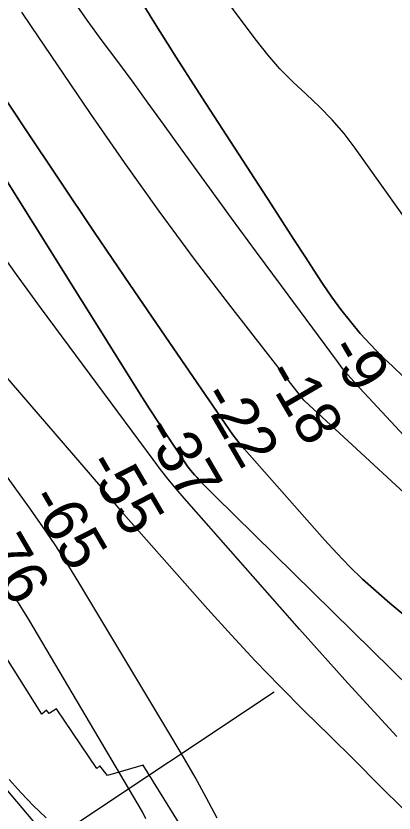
# Model space of a CAD drawing. Extents: x 3297753 to 3335611, y 652252 to 677623.
# Drawn here: x 3309808 to 3310374, y 670586 to 671780 of the extents above; entities that cross this region are included whole.
import ezdxf

# ---------------------------------------------------------------- set-up
doc = ezdxf.new("R2010")
doc.units = 0
for name, color, linetype in [('V-CHAN-NAID', 7, 'Continuous'), ('V-RIVR-RANG', 7, 'Continuous'), ('V-RRAP-RVMT', 7, 'Continuous'), ('V-TOPO-DPTH', 7, 'Continuous'), ('V-TOPO-MAJR', 7, 'Continuous'), ('V-TOPO-MINR', 7, 'Continuous')]:
    doc.layers.add(name, color=color, linetype=linetype)

msp = doc.modelspace()

# ---------------------------------------------------------------- linework, layer by layer
at = {"layer": 'V-RIVR-RANG'}
msp.add_line((3308878.8, 669892.6), (3310194.6, 670767.2), dxfattribs=at)
at = {"layer": 'V-RRAP-RVMT'}
for p, q in [((3309846.4, 670733.9), (3309768.1, 670857.3)), ((3309853.8, 670739.8), (3309846.4, 670733.9)), ((3309857.6, 670735.1), (3309853.8, 670739.8)), ((3309868.4, 670742.1), (3309857.6, 670735.1)), ((3309928.8, 670652.6), (3309868.4, 670742.1)), ((3309933.3, 670656.4), (3309928.8, 670652.6)), ((3309945.1, 670642.1), (3309933.3, 670656.4)), ((3309998.2, 670657.4), (3309945.1, 670642.1)), ((3310074.3, 670535.2), (3309998.2, 670657.4))]:
    msp.add_line(p, q, dxfattribs=at)
at = {"layer": 'V-TOPO-DPTH'}
for points in [[(3309973.3, 671839), (3310010.5, 671777.9), (3310048.4, 671717.3), (3310086.9, 671657.1), (3310189.9, 671498), (3310207, 671471.5), (3310224.2, 671445), (3310241.4, 671418.5), (3310258.5, 671392), (3310267.8, 671377.7), (3310280.8, 671358.7), (3310294.3, 671340.1), (3310308.6, 671322.1), (3310323.4, 671304.5), (3310339, 671287.6), (3310354.9, 671271), (3310371.5, 671255.1), (3310388.4, 671239.5)], [(3310388.4, 671239.5), (3310371.5, 671255.1), (3310354.9, 671271), (3310339, 671287.6), (3310323.4, 671304.5), (3310308.6, 671322.1), (3310294.3, 671340.1), (3310280.8, 671358.7), (3310267.8, 671377.7), (3310258.5, 671392), (3310241.4, 671418.5), (3310224.2, 671445), (3310207, 671471.5), (3310189.9, 671498), (3310086.9, 671657.1), (3310048.4, 671717.3), (3310010.5, 671777.9), (3309973.3, 671839)], [(3309610, 671826.9), (3309979.7, 671235.6), (3309993.7, 671213.3), (3310007.9, 671191.2), (3310022.3, 671169.2), (3310036.8, 671147.2), (3310065.1, 671104.7), (3310065.6, 671104.1), (3310066.9, 671102.3), (3310075.3, 671092.6), (3310079, 671088.4), (3310082.7, 671084.3), (3310086.5, 671080.2), (3310090.3, 671076.3), (3310094.2, 671072.3), (3310098.2, 671068.4), (3310102.1, 671064.5), (3310106, 671060.6), (3310458.1, 670714.2)], [(3310458.1, 670714.2), (3310106, 671060.6), (3310102.1, 671064.5), (3310098.2, 671068.4), (3310094.2, 671072.3), (3310090.3, 671076.3), (3310086.5, 671080.2), (3310082.7, 671084.3), (3310079, 671088.4), (3310075.3, 671092.6), (3310066.9, 671102.3), (3310065.6, 671104.1), (3310065.1, 671104.7), (3310036.8, 671147.2), (3310022.3, 671169.2), (3310007.9, 671191.2), (3309993.7, 671213.3), (3309979.7, 671235.6), (3309610, 671826.9)], [(3309698.7, 671796.3), (3309820.8, 671612.2), (3309873, 671533.9), (3309925.5, 671455.8), (3309978.3, 671377.9), (3310031.3, 671300.1), (3310127.3, 671160.2), (3310132.7, 671152.6), (3310138.2, 671145.2), (3310144.1, 671138), (3310150.1, 671130.9), (3310269.8, 670995), (3310288.3, 670974.9), (3310307.2, 670955.3), (3310326.9, 670936.4), (3310347.1, 670918), (3310367.8, 670900.2), (3310388.8, 670882.7)], [(3310388.8, 670882.7), (3310367.8, 670900.2), (3310347.1, 670918), (3310326.9, 670936.4), (3310307.2, 670955.3), (3310288.3, 670974.9), (3310269.8, 670995), (3310150.1, 671130.9), (3310144.1, 671138), (3310138.2, 671145.2), (3310132.7, 671152.6), (3310127.3, 671160.2), (3310031.3, 671300.1), (3309978.3, 671377.9), (3309925.5, 671455.8), (3309873, 671533.9), (3309820.8, 671612.2), (3309698.7, 671796.3)], [(3310552.4, 670914.9), (3310246.5, 671197.5), (3310245.7, 671198.2), (3310243.9, 671199.7), (3310243.1, 671200.4), (3310239.9, 671203.3), (3310239.1, 671204.2), (3310238.8, 671204.6), (3310129.6, 671344.8), (3310075.4, 671415.8), (3310022.1, 671487.5), (3309970.3, 671560.3), (3309919.4, 671633.8), (3309831, 671764.2), (3309816.6, 671785.7)], [(3310552.4, 670914.9), (3310246.5, 671197.5), (3310245.7, 671198.2), (3310243.9, 671199.7), (3310243.1, 671200.4), (3310239.9, 671203.3), (3310239.1, 671204.2), (3310238.8, 671204.6), (3310129.6, 671344.8), (3310075.4, 671415.8), (3310022.1, 671487.5), (3309970.3, 671560.3), (3309919.4, 671633.8), (3309831, 671764.2), (3309816.6, 671785.7)]]:
    msp.add_lwpolyline(points, dxfattribs=at)
at = {"layer": 'V-TOPO-MAJR'}
msp.add_lwpolyline([(3310378.3, 670700.6), (3310305, 670780.4), (3310232.6, 670861.2), (3310059.7, 671057.6), (3310047.6, 671071.7), (3310035.8, 671086), (3310024.3, 671100.6), (3310013.1, 671115.4), (3309844.7, 671343), (3309808.5, 671392.6), (3309772.7, 671442.5), (3309737.4, 671492.7), (3309702.5, 671543.3), (3309700.5, 671546.2), (3309667.1, 671595.6), (3309633.8, 671645), (3309600.8, 671694.7), (3309567.9, 671744.4), (3309527.8, 671805.6)], dxfattribs=at)
at = {"layer": 'V-TOPO-MINR'}
for points in [[(3308758.8, 672065.7), (3308996.7, 671601), (3308998.4, 671597.8), (3309000.1, 671594.6), (3309001.9, 671591.5), (3309003.7, 671588.4), (3309017.8, 671565.5), (3309020.8, 671560.8), (3309024, 671556.2), (3309027.4, 671551.7), (3309030.9, 671547.4), (3309034.6, 671543.2), (3309594.9, 670863.7), (3309602.6, 670851.4), (3309610.7, 670839.4), (3309619.3, 670827.8), (3309628.4, 670816.5), (3309932.1, 670456.8)], [(3310388.4, 671239.5), (3310371.5, 671255.1), (3310354.9, 671271), (3310339, 671287.6), (3310323.4, 671304.5), (3310308.6, 671322.1), (3310294.3, 671340.1), (3310280.8, 671358.7), (3310267.8, 671377.7), (3310258.5, 671392), (3310241.4, 671418.5), (3310224.2, 671445), (3310207, 671471.5), (3310189.9, 671498), (3310086.9, 671657.1), (3310048.4, 671717.3), (3310010.5, 671777.9), (3309973.3, 671839)], [(3310458.1, 670714.2), (3310106, 671060.6), (3310102.1, 671064.5), (3310098.2, 671068.4), (3310094.2, 671072.3), (3310090.3, 671076.3), (3310086.5, 671080.2), (3310082.7, 671084.3), (3310079, 671088.4), (3310075.3, 671092.6), (3310066.9, 671102.3), (3310065.6, 671104.1), (3310065.1, 671104.7), (3310036.8, 671147.2), (3310022.3, 671169.2), (3310007.9, 671191.2), (3309993.7, 671213.3), (3309979.7, 671235.6), (3309610, 671826.9)], [(3310473.8, 671360.4), (3310315.9, 671581.9), (3310299.3, 671603.7), (3310281.6, 671624.6), (3310262.5, 671644.1), (3310242.4, 671662.8), (3310222.3, 671681.5), (3310203, 671700.9), (3310185.1, 671721.6), (3310167.9, 671743), (3310143.4, 671775.9), (3310115.4, 671814.9)], [(3310436, 671100.4), (3310322.2, 671222.6), (3310313.6, 671232.2), (3310305.2, 671241.9), (3310297.1, 671252), (3310289.3, 671262.2), (3310205.3, 671375.6), (3310168, 671426.2), (3310130.8, 671476.9), (3310093.8, 671527.8), (3310057, 671578.7), (3310028.7, 671618.1), (3310006, 671649.4), (3309983.2, 671680.6), (3309960.3, 671711.6), (3309937.2, 671742.6), (3309914.5, 671773.8), (3309892.5, 671805.5)], [(3310389.2, 670590.5), (3310352, 670627.7), (3310314.8, 670664.8), (3310277.4, 670701.8), (3310239.9, 670738.6), (3310202.8, 670775.9), (3310166.2, 670813.6), (3310130.4, 670852.1), (3310095.2, 670891.1), (3309976.3, 671025.6), (3309968.9, 671034.1), (3309961.7, 671042.8), (3309954.6, 671051.6), (3309947.7, 671060.6), (3309349.5, 671754.1), (3309342.6, 671764.8), (3309336.2, 671775.9), (3309330.2, 671787.2)], [(3310388.8, 670882.7), (3310367.8, 670900.2), (3310347.1, 670918), (3310326.9, 670936.4), (3310307.2, 670955.3), (3310288.3, 670974.9), (3310269.8, 670995), (3310150.1, 671130.9), (3310144.1, 671138), (3310138.2, 671145.2), (3310132.7, 671152.6), (3310127.3, 671160.2), (3310031.3, 671300.1), (3309978.3, 671377.9), (3309925.5, 671455.8), (3309873, 671533.9), (3309820.8, 671612.2), (3309698.7, 671796.3)], [(3310552.4, 670914.9), (3310246.5, 671197.5), (3310245.7, 671198.2), (3310243.9, 671199.7), (3310243.1, 671200.4), (3310239.9, 671203.3), (3310239.1, 671204.2), (3310238.8, 671204.6), (3310129.6, 671344.8), (3310075.4, 671415.8), (3310022.1, 671487.5), (3309970.3, 671560.3), (3309919.4, 671633.8), (3309831, 671764.2), (3309816.6, 671785.7)], [(3310109, 670578.3), (3310092.7, 670608.9), (3310076, 670639.3), (3310058.8, 670669.3), (3310041.3, 670699.2), (3309903.7, 670928.8), (3309885.5, 670958.3), (3309866.7, 670987.6), (3309847.2, 671016.3), (3309827.1, 671044.6), (3309734.6, 671171.8)], [(3310002.4, 670577.3), (3309997.2, 670587.5), (3309827, 670875.8), (3309806.9, 670908.6)], [(3309797.9, 670635.8), (3309815.5, 670616), (3309833.8, 670596.9), (3309853, 670578.8)]]:
    msp.add_lwpolyline(points, dxfattribs=at)

# ---------------------------------------------------------------- texts
at = {"layer": 'V-CHAN-NAID'}
msp.add_text('DOW-MISSOURI (221.8) (4)', height=100, rotation=42.843, dxfattribs=at).set_placement((3310408.3, 669839.5))
at = {"layer": 'V-RIVR-RANG'}
for s, p in [('-9', (3310273.3, 671279.9)), ('-18', (3310178.7, 671243.7)), ('-22', (3310082.6, 671210)), ('-37', (3309997, 671158.2)), ('-55', (3309910.6, 671107.9)), ('-65', (3309825.2, 671055.9)), ('-76', (3309739.2, 671004.8))]:
    msp.add_text(s, height=67, rotation=300.2348, dxfattribs=at).set_placement(p)

doc.saveas('drawing.dxf')
